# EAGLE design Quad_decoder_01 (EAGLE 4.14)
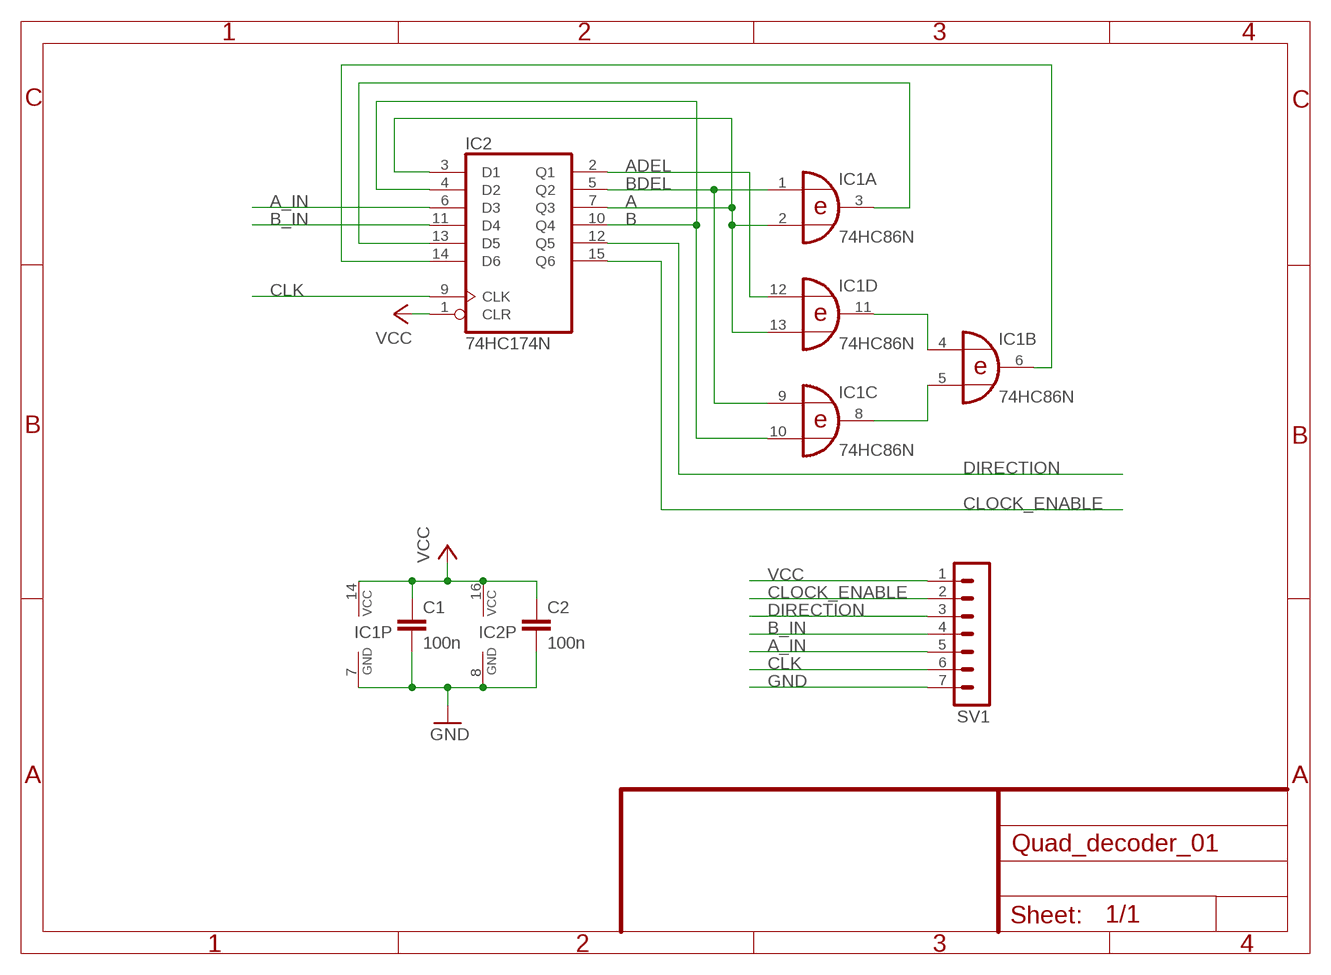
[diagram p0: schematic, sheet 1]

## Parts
C1  100n  C-EU025-024X044  [C025-024X044]
C2  100n  C-EU025-024X044  [C025-024X044]
IC1  74HC86N  [DIL14]
IC2  74HC174N  [DIL16]
SV1  MA07-1  [MA07-1]

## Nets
A: IC1.2(A:I1) IC1.13(D:I1) IC2.3(D1) IC2.7(Q3)
A_IN: IC2.6(D3) SV1.5
ADEL: IC1.12(D:I0) IC2.2(Q1)
B: IC1.10(C:I1) IC2.4(D2) IC2.10(Q4)
B_IN: IC2.11(D4) SV1.4
BDEL: IC1.1(A:I0) IC1.9(C:I0) IC2.5(Q2)
CLK: IC2.9(CLK) SV1.6
CLOCK_ENABLE: IC2.15(Q6) SV1.2
DIRECTION: IC2.12(Q5) SV1.3
GND: C1.2 C2.2 IC1.7(P:GND) IC2.8(GND) SV1.7
N$1: IC1.4(B:I0) IC1.11(D:O)
N$2: IC1.5(B:I1) IC1.8(C:O)
N$5: IC1.3(A:O) IC2.13(D5)
N$6: IC1.6(B:O) IC2.14(D6)
VCC: C1.1 C2.1 IC1.14(P:VCC) IC2.1(CLR) IC2.16(VCC) SV1.1

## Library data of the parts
C1 C2 = rcl:C-EU: CAPACITOR, European symbol
IC1 = 74xx-eu:74*86: Quad 2-input EXCLUSIVE-OR (XOR) gate
IC2 = 74xx-eu:74*174: Hex D type FLIP FLOP, clear
SV1 = con-lstb:MA07-1: PIN HEADER

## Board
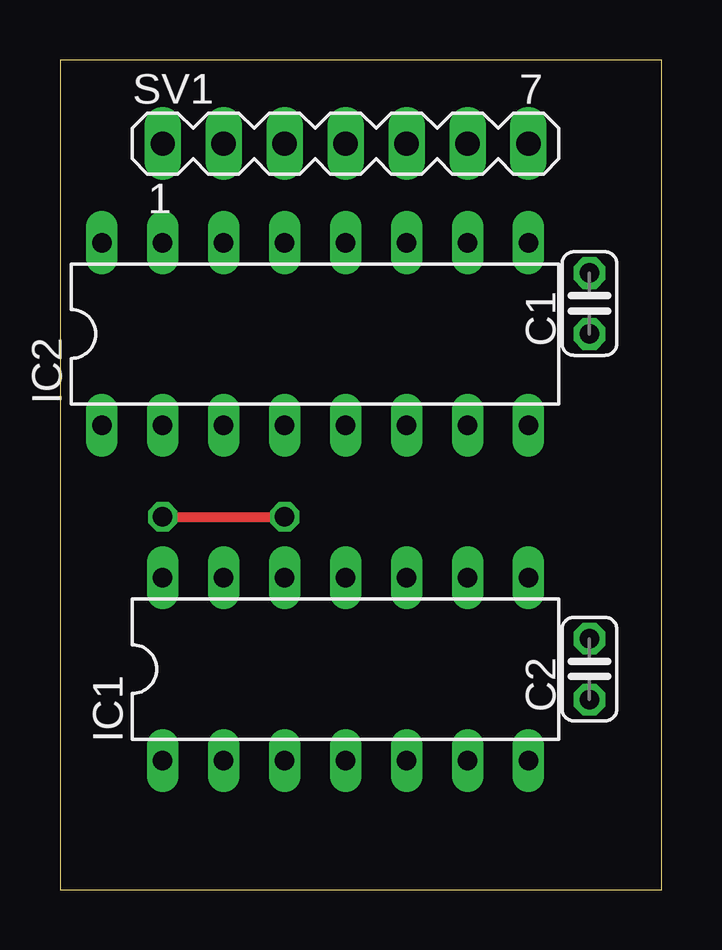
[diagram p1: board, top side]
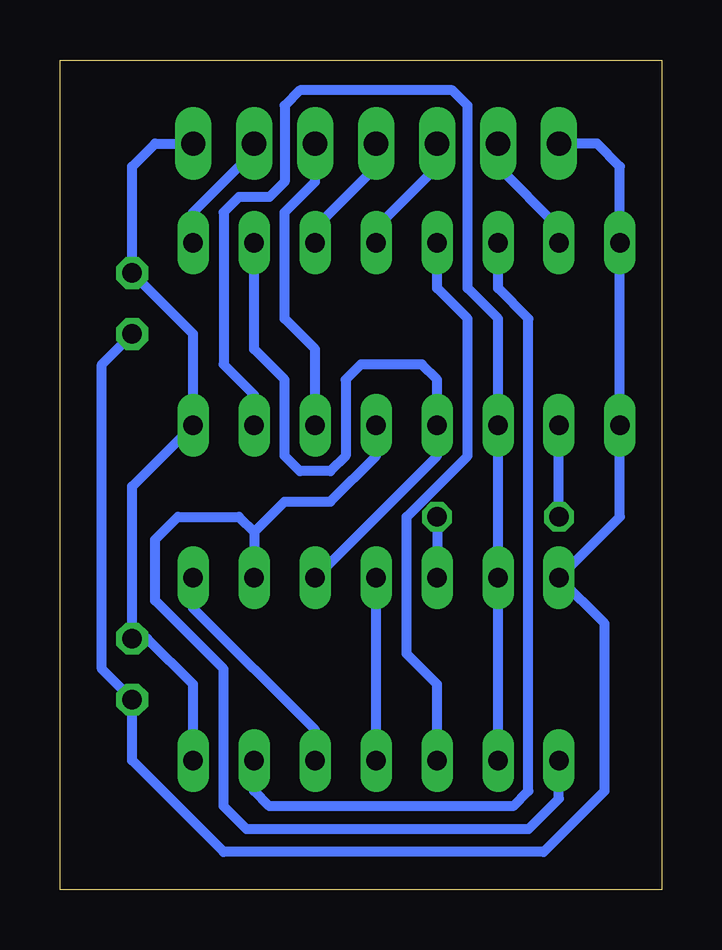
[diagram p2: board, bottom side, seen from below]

Size 25.07 x 34.6 mm. Coordinates in mm from the lower left corner, seen from the top.
Outline: 0,0 25.07,0 25.07,34.6 0,34.6 0,0
Copper layers (1*16): Top 0.035mm / dielectric 1.5mm / Bottom 0.035mm
Design rules "default": minimum track width 10mil, minimum drill 24mil, track to track 12mil, track to pad 12mil, pad to pad 12mil, via to via 12mil, smd to smd 12mil, copper to edge 40mil, drill to drill 8mil, minimum pad ring 10mil, minimum via ring 8mil, stop-mask expansion 4mil, vias tented up to drill 0mil, thermal gap 10mil

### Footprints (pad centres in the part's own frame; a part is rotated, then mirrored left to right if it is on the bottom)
C025-024X044 = drill 0.813 octagon: 1 -1.27,0; 2 1.27,0
DIL14 = drill 0.813 long: 1 -7.62,-3.81; 2 -5.08,-3.81; 3 -2.54,-3.81; 4 0,-3.81; 5 2.54,-3.81; 6 5.08,-3.81; 7 7.62,-3.81; 8 7.62,3.81; 9 5.08,3.81; 10 2.54,3.81; 11 0,3.81; 12 -2.54,3.81; 13 -5.08,3.81; 14 -7.62,3.81
DIL16 = drill 0.813 long: 1 -8.89,-3.81; 2 -6.35,-3.81; 3 -3.81,-3.81; 4 -1.27,-3.81; 5 1.27,-3.81; 6 3.81,-3.81; 7 6.35,-3.81; 8 8.89,-3.81; 9 8.89,3.81; 10 6.35,3.81; 11 3.81,3.81; 12 1.27,3.81; 13 -1.27,3.81; 14 -3.81,3.81; 15 -6.35,3.81; 16 -8.89,3.81
MA07-1 = drill 1.016 long: 1 -7.62,0; 2 -5.08,0; 3 -2.54,0; 4 0,0; 5 2.54,0; 6 5.08,0; 7 7.62,0

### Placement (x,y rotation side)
C1  22.06,24.44 90 top
C2  22.06,9.2 90 top
IC1  11.9,9.2 0 top
IC2  10.63,23.17 0 top
SV1  11.9,31.11 0 top

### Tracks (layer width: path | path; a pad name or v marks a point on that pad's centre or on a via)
A
  Bottom 0.406: IC1.2 IC1.13 IC2.3 6.82,23.81 8.09,25.08 8.09,32.7 8.73,33.33 15.08,33.33 15.71,32.7 15.71,29.52 16.34,28.89 17.61,28.89 18.25,28.25 18.25,21.9 16.98,20.63 IC2.7
A_IN
  Bottom 0.406: IC2.6 14.44,22.54 15.71,23.81 15.71,28.25 14.44,29.52 SV1.5
ADEL  (via drill 0.81)
  Top 0.406: v4.28,15.55 v9.36,15.55
  Bottom 0.406: v9.36,15.55 IC1.12 | v4.28,15.55 IC2.2
B
  Bottom 0.406: IC1.10 9.36,18.09 IC2.4 9.36,21.27 10,21.9 12.54,21.9 13.17,21.27 13.17,18.09 13.81,17.46 15.08,17.46 15.71,18.09 15.71,21.27 16.98,22.54 IC2.10
B_IN
  Bottom 0.406: IC2.11 14.44,27.62 11.9,30.16 SV1.4
BDEL
  Bottom 0.406: 16.98,14.92 IC1.9 | 16.98,14.92 15.71,16.19 13.81,16.19 11.9,18.09 IC2.5 | IC1.1 4.28,3.8 5.55,2.54 17.3,2.54 18.25,3.49 18.25,9.2 21.11,12.06 21.11,14.6 20.15,15.55 17.61,15.55 16.98,14.92
CLK
  Bottom 0.406: SV1.6 16.98,30.79 19.52,28.25 IC2.9
CLOCK_ENABLE
  Bottom 0.406: SV1.2 6.82,30.16 4.28,27.62 IC2.15
DIRECTION
  Bottom 0.406: SV1.3 9.36,30.16 11.9,27.62 IC2.12
GND
  Bottom 0.406: SV1.7 21.11,31.11 22.06,30.16 C1.2 19.52,23.17 IC2.8 22.06,16.82 C2.2 21.42,10.47 19.52,8.57 IC1.7
N$1
  Bottom 0.406: IC1.4 IC1.11
N$2
  Bottom 0.406: IC1.8 19.52,11.74 14.44,6.66 IC1.5
N$5
  Bottom 0.406: IC2.13 9.36,25.08 8.09,23.81 8.09,18.09 10.63,15.55 10.63,9.84 9.36,8.57 IC1.3
N$6
  Bottom 0.406: IC2.14 6.82,25.08 5.55,23.81 5.55,4.12 6.18,3.49 16.34,3.49 16.98,4.12 IC1.6
VCC
  Bottom 0.406: SV1.1 2.69,31.11 1.74,30.16 IC2.16 IC2.1 1.74,15.55 IC1.14 2.38,11.11 2.38,4.12 4.92,1.58 18.25,1.58 22.06,5.39 C2.1 23.33,9.2 23.33,21.9 C1.1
